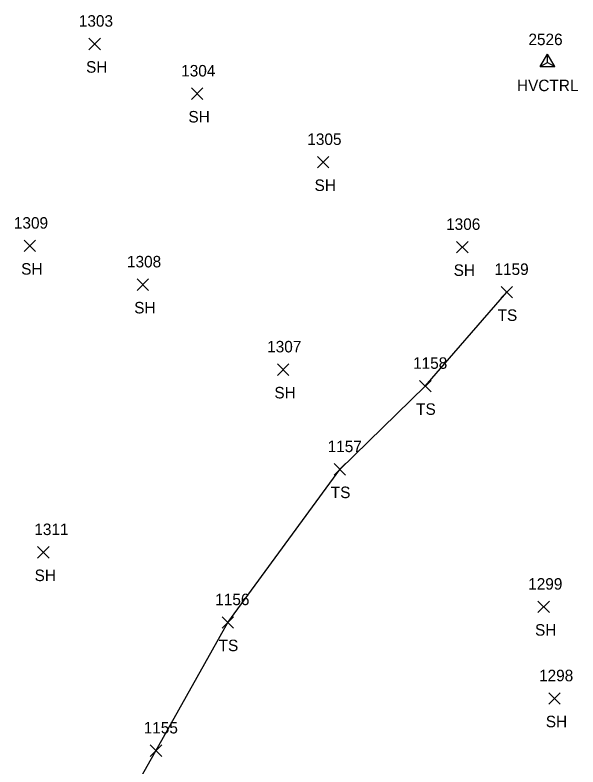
# Model space of a CAD drawing. Extents: x 1885914 to 1887218, y 756253 to 760620.
# Drawn here: x 1886740.8 to 1886838.7, y 760195 to 760325.7 of the extents above; entities that cross this region are included whole.
import ezdxf

# ---------------------------------------------------------------- set-up
doc = ezdxf.new("R2010")
doc.units = 0
for name, color, linetype in [('C_A', 7, 'Continuous'), ('C_I', 7, 'Continuous'), ('CPSM', 7, 'Continuous'), ('L_A', 7, 'Continuous'), ('L_I', 7, 'Continuous'), ('L_TIC', 7, 'Continuous'), ('LELB', 7, 'Continuous')]:
    doc.layers.add(name, color=color, linetype=linetype)

msp = doc.modelspace()

# ---------------------------------------------------------------- linework, layer by layer
at = {"layer": 'CPSM'}
for p, q in [((1886832.17, 760316.77), (1886833.42, 760318.93)), ((1886834.67, 760316.77), (1886833.42, 760318.93)), ((1886833.42, 760317.49), (1886833.42, 760318.93)), ((1886832.17, 760316.77), (1886833.42, 760317.49)), ((1886833.42, 760317.49), (1886833.42, 760317.49)), ((1886833.42, 760317.49), (1886834.67, 760316.77)), ((1886832.17, 760316.77), (1886834.67, 760316.77))]:
    msp.add_line(p, q, dxfattribs=at)
at = {"layer": 'L_TIC'}
for points in [[(1886753.64, 760319.7), (1886755.64, 760321.7)], [(1886755.64, 760319.7), (1886753.64, 760321.7)], [(1886771.45, 760311.04), (1886773.45, 760313.04)], [(1886773.45, 760311.04), (1886771.45, 760313.04)], [(1886793.4, 760299.13), (1886795.4, 760301.13)], [(1886795.4, 760299.13), (1886793.4, 760301.13)], [(1886742.35, 760284.58), (1886744.35, 760286.58)], [(1886744.35, 760284.58), (1886742.35, 760286.58)], [(1886817.6, 760284.36), (1886819.6, 760286.36)], [(1886819.6, 760284.36), (1886817.6, 760286.36)], [(1886762.02, 760277.84), (1886764.02, 760279.84)], [(1886764.02, 760277.84), (1886762.02, 760279.84)], [(1886825.33, 760276.53), (1886827.33, 760278.53)], [(1886827.33, 760276.53), (1886825.33, 760278.53)], [(1886786.42, 760263.06), (1886788.42, 760265.06)], [(1886788.42, 760263.06), (1886786.42, 760265.06)], [(1886811.15, 760260.2), (1886813.15, 760262.2)], [(1886813.15, 760260.2), (1886811.15, 760262.2)], [(1886796.3, 760245.72), (1886798.3, 760247.72)], [(1886798.3, 760245.72), (1886796.3, 760247.72)], [(1886744.69, 760231.29), (1886746.69, 760233.29)], [(1886746.69, 760231.29), (1886744.69, 760233.29)], [(1886831.76, 760221.8), (1886833.76, 760223.8)], [(1886833.76, 760221.8), (1886831.76, 760223.8)], [(1886776.79, 760219.1), (1886778.79, 760221.1)], [(1886778.79, 760219.1), (1886776.79, 760221.1)], [(1886833.64, 760205.87), (1886835.64, 760207.87)], [(1886835.64, 760205.87), (1886833.64, 760207.87)], [(1886764.29, 760196.79), (1886766.29, 760198.79)], [(1886766.29, 760196.79), (1886764.29, 760198.79)]]:
    msp.add_lwpolyline(points, dxfattribs=at)
at = {"layer": 'LELB'}
msp.add_lwpolyline([(1886760.47, 760189.26), (1886765.29, 760197.79), (1886777.79, 760220.1), (1886797.3, 760246.72), (1886812.15, 760261.2), (1886826.33, 760277.53)], dxfattribs=at)

# ---------------------------------------------------------------- texts
at = {"layer": 'C_A'}
msp.add_text('HVCTRL', height=2, dxfattribs=at).set_placement((1886828.11, 760312.49))
at = {"layer": 'C_I'}
msp.add_text('2526', height=2, dxfattribs=at).set_placement((1886830.1, 760320.49))
at = {"layer": 'L_A'}
for s, p in [('SH', (1886753.13, 760315.7)), ('SH', (1886770.94, 760307.04)), ('SH', (1886792.89, 760295.13)), ('SH', (1886741.84, 760280.58)), ('SH', (1886817.09, 760280.36)), ('SH', (1886761.51, 760273.84)), ('TS', (1886824.74, 760272.53)), ('SH', (1886785.9, 760259.06)), ('TS', (1886810.56, 760256.2)), ('TS', (1886795.71, 760241.72)), ('SH', (1886744.18, 760227.29)), ('SH', (1886831.25, 760217.8)), ('TS', (1886776.2, 760215.1)), ('SH', (1886833.13, 760201.87))]:
    msp.add_text(s, height=2, dxfattribs=at).set_placement(p)
at = {"layer": 'L_I'}
for s, p in [('1303', (1886751.87, 760323.7)), ('1304', (1886769.68, 760315.04)), ('1305', (1886791.63, 760303.13)), ('1309', (1886740.57, 760288.58)), ('1306', (1886815.78, 760288.36)), ('1308', (1886760.25, 760281.84)), ('1159', (1886824.19, 760280.53)), ('1307', (1886784.64, 760267.06)), ('1158', (1886810.03, 760264.2)), ('1157', (1886795.17, 760249.72)), ('1311', (1886744.13, 760235.29)), ('1299', (1886830.06, 760225.8)), ('1156', (1886775.61, 760223.1)), ('1298', (1886831.95, 760209.87)), ('1155', (1886763.16, 760200.79))]:
    msp.add_text(s, height=2, dxfattribs=at).set_placement(p)

doc.saveas('drawing.dxf')
